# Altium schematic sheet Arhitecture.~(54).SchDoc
size A3; SheetNumber: 1; SheetTotal: 14
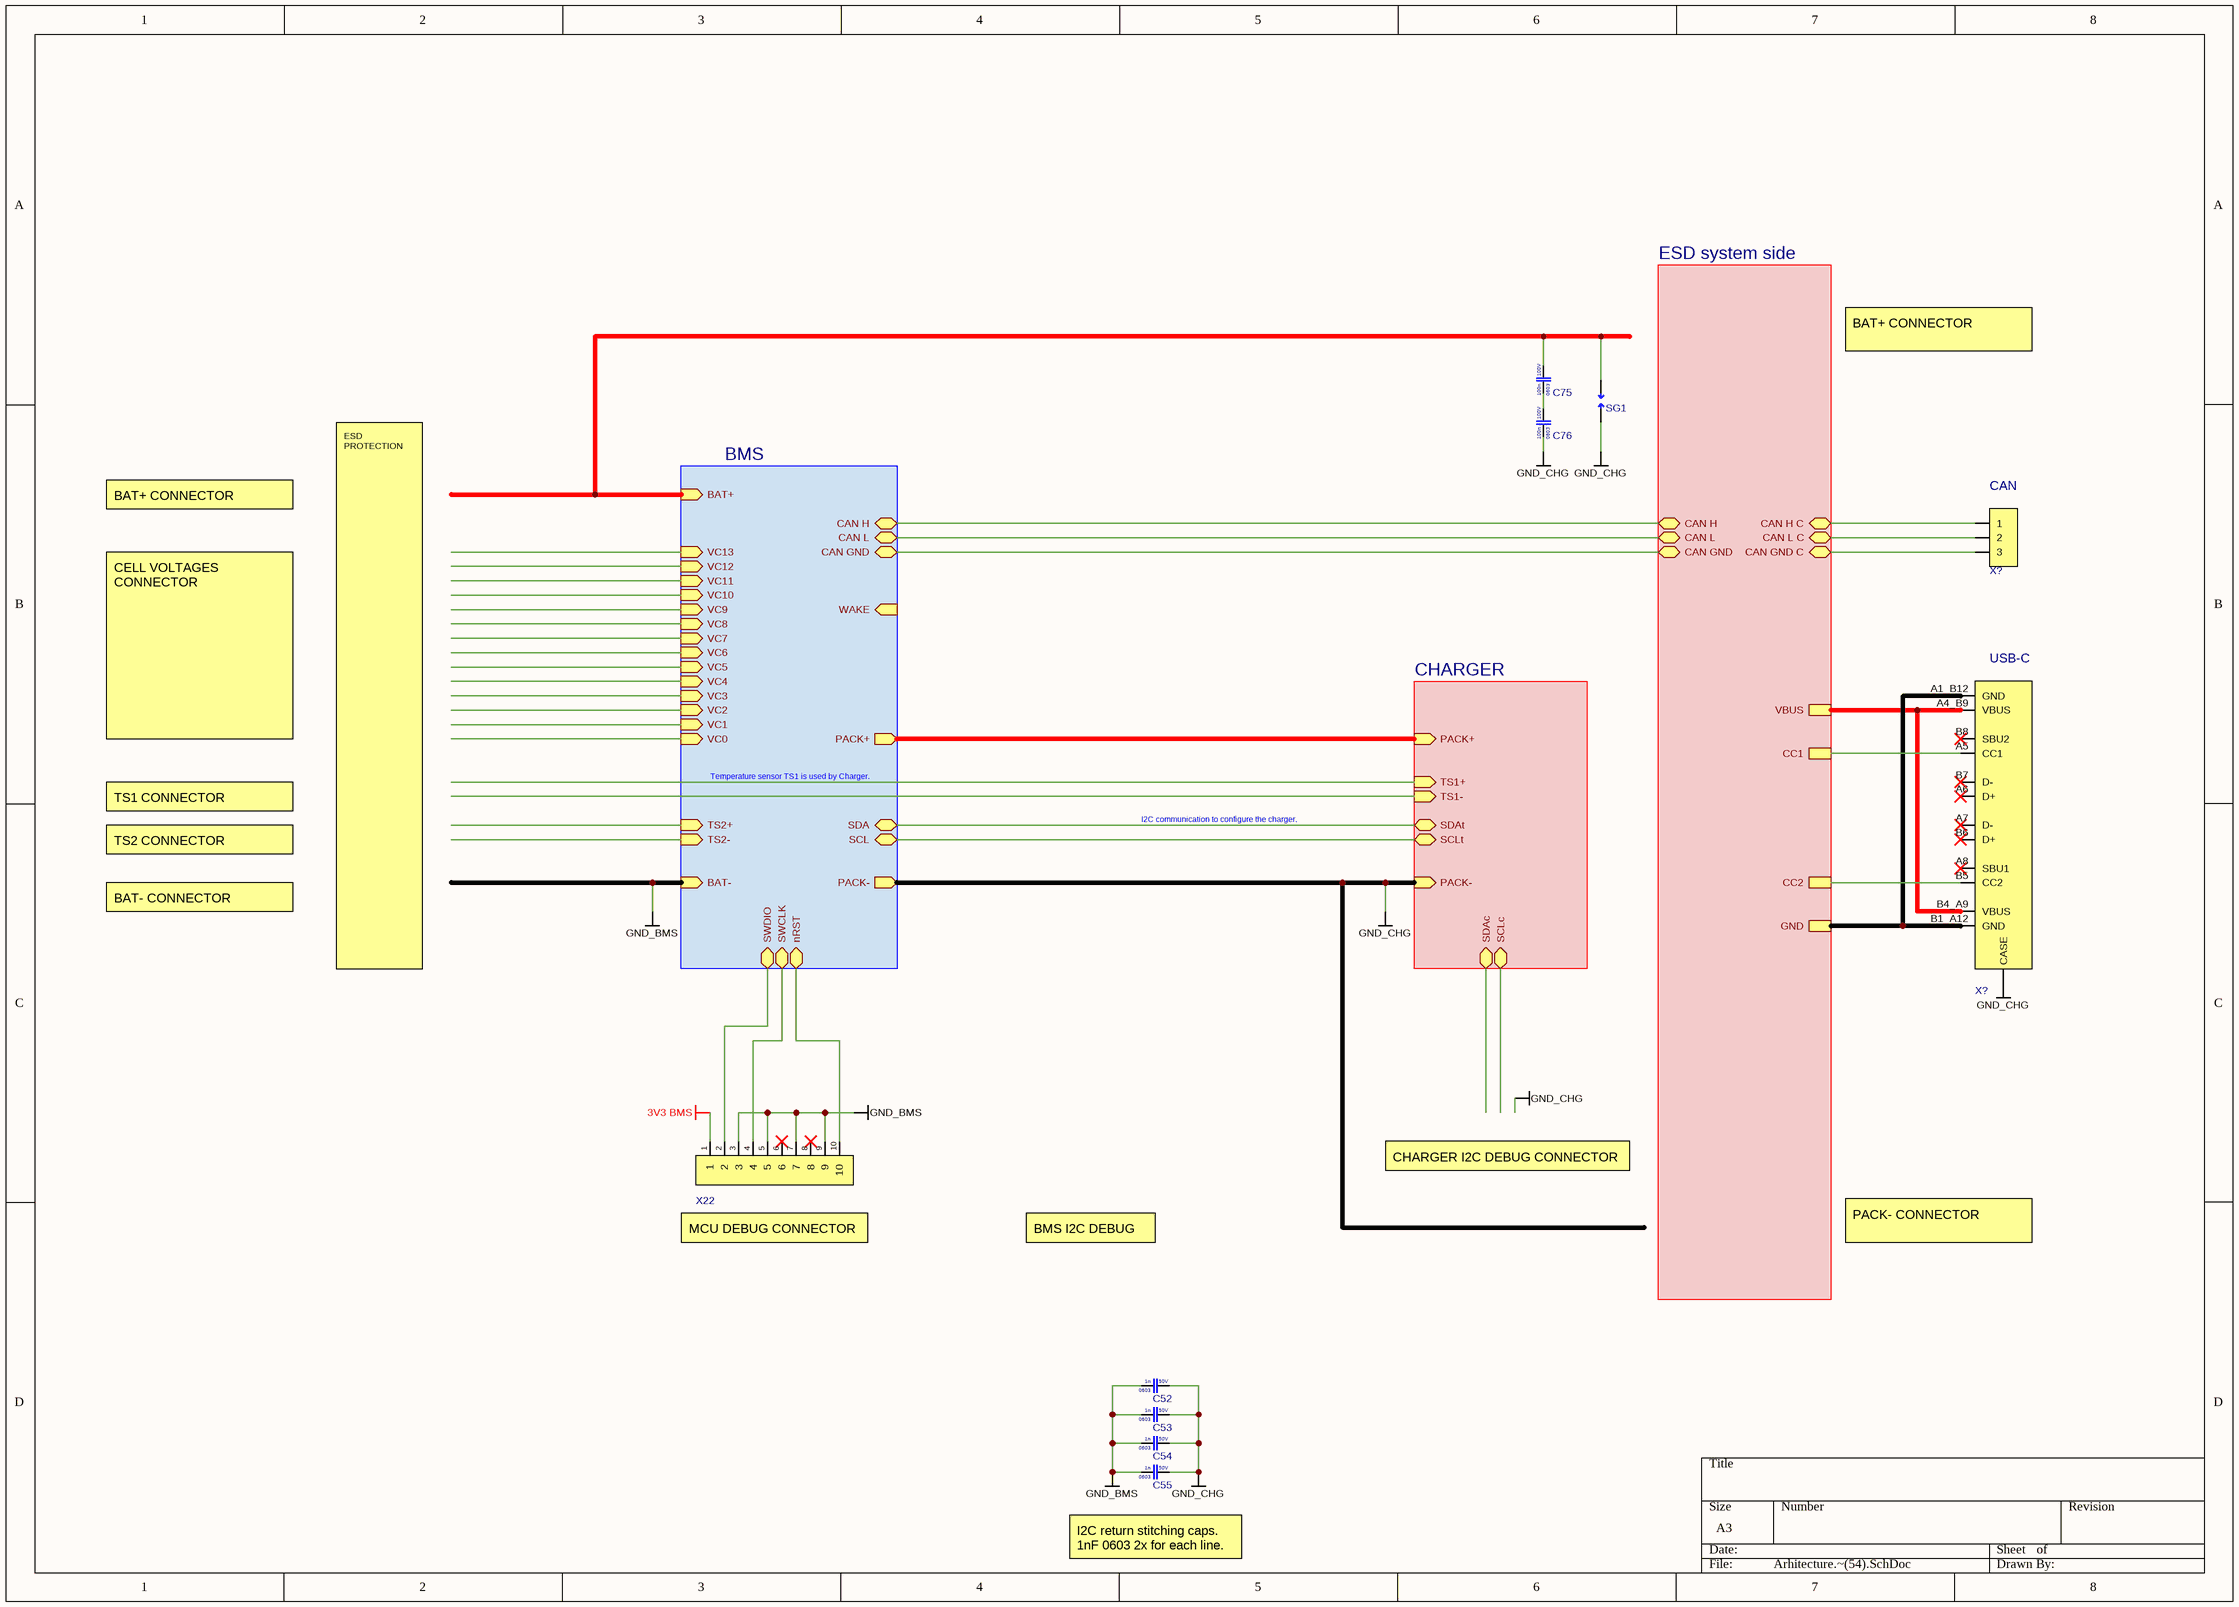
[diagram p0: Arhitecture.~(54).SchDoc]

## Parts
(Parts that share a designator on the sheet are numbered #1, #2 ... from top to bottom, then left to right.)
C52  Voltage Rating: 50V  Case Code (Imperial): 0603  Capacitance: 1n  [CAP 0603]  (hidden comment: CL10B102KB8NNNC)
C53  Voltage Rating: 50V  Case Code (Imperial): 0603  Capacitance: 1n  [CAP 0603]  (hidden comment: CL10B102KB8NNNC)
C54  Voltage Rating: 50V  Case Code (Imperial): 0603  Capacitance: 1n  [CAP 0603]  (hidden comment: CL10B102KB8NNNC)
C55  Voltage Rating: 50V  Case Code (Imperial): 0603  Capacitance: 1n  [CAP 0603]  (hidden comment: CL10B102KB8NNNC)
C75  Voltage Rating: 100V  Case Code (Imperial): 0603  Capacitance: 100n  [CAP 0603]  (hidden comment: CC0603KRX7R0BB104)
C76  Voltage Rating: 100V  Case Code (Imperial): 0603  Capacitance: 100n  [CAP 0603]  (hidden comment: CC0603KRX7R0BB104)
SG1  Spark gap  [Spark Gap 0.270mm]  (value not drawn)  (no BOM)
X22  HX IDC127-2-05-S-4.9  [JTAG Cortex connector]  (value not drawn)
X?#1  S3B-XH-A-1(LF)(SN)  [S3B-XH-A-1(LF)(SN)]  (value not drawn)
X?#2  USB-TYPE-C-018  [TYPE-C 16PIN 2MD]  (value not drawn)

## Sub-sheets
BMS = BMS.SchDoc: BAT+ (in), BAT- (in), VC0 (in), VC1 (in), VC2 (in), VC3 (in), VC4 (in), VC5 (in), VC6 (in), VC7 (in), VC8 (in), VC9 (in), VC10 (in), VC11 (in), VC12 (in), VC13 (in), PACK+ (out), PACK- (out), SCL (bidir), SDA (bidir), CAN H (bidir), CAN L (bidir), TS2+ (in), TS2- (in), WAKE (in), SWDIO (bidir), SWCLK (bidir), nRST (bidir), CAN GND (bidir)
CHARGER = CHARGER.SchDoc: PACK+ (in), PACK- (in), SDAt (bidir), SCLt (bidir), TS1+ (in), TS1- (in), SDAc (bidir), SCLc (bidir)
ESD system side = ESD system side.SchDoc: CAN H (bidir), CAN L (bidir), CAN GND (bidir), CAN H C (bidir), CAN L C (bidir), CAN GND C (bidir), VBUS, GND, CC1, CC2

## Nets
3V3 BMS: X22.1
GND_BMS: C52.1 C53.1 C54.1 C55.1 X22.3 X22.5 X22.7 X22.9 ; sheet BMS/BAT-
GND_CHG: C52.2 C53.2 C54.2 C55.2 C76.1 SG1.1 X?#2.CASE ; sheet BMS/PACK-, sheet CHARGER/PACK-
NetC75_1: C75.1 C76.2
NetC75_2: C75.2 SG1.2 ; sheet BMS/BAT+
NetX22_2: X22.2 ; sheet BMS/SWDIO
NetX22_4: X22.4 ; sheet BMS/SWCLK
NetX22_10: X22.10 ; sheet BMS/nRST
NetX?#1_1: X?#1.1 ; sheet ESD system side/CAN H C
NetX?#1_2: X?#1.2 ; sheet ESD system side/CAN L C
NetX?#1_3: X?#1.3 ; sheet ESD system side/CAN GND C
NetX?#2_A1_B12: X?#2.A1_B12(GND) X?#2.B1_A12(GND) ; sheet ESD system side/GND
NetX?#2_A4_B9: X?#2.A4_B9(VBUS) X?#2.B4_A9(VBUS) ; sheet ESD system side/VBUS
NetX?#2_A5: X?#2.A5(CC1) ; sheet ESD system side/CC1
NetX?#2_B5: X?#2.B5(CC2) ; sheet ESD system side/CC2
(unnamed): sheet BMS/PACK+, sheet CHARGER/PACK+
(unnamed): sheet BMS/SCL, sheet CHARGER/SCLt  [a separate net that carries the same name]
(unnamed): sheet BMS/SDA, sheet CHARGER/SDAt  [a separate net that carries the same name]
(unnamed): sheet BMS/CAN H, sheet ESD system side/CAN H  [a separate net that carries the same name]
(unnamed): sheet BMS/CAN L, sheet ESD system side/CAN L  [a separate net that carries the same name]
(unnamed): sheet BMS/CAN GND, sheet ESD system side/CAN GND  [a separate net that carries the same name]

Not connected (* = marked no-connect by the designer): X22 6* 8*; X?#2 A6(D+)* A7(D-)* A8(SBU1)* B6(D+)* B7(D-)* B8(SBU2)*

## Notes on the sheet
- BAT+ CONNECTOR
- (near X?#1) CAN
- (near X?#2) USB-C
- CELL VOLTAGES CONNECTOR
- TS1 CONNECTOR
- Temperature sensor TS1 is used by Charger.
- I2C communication to configure the charger.
- BAT- CONNECTOR
- TS2 CONNECTOR
- ESD PROTECTION
- CHARGER I2C DEBUG CONNECTOR
- MCU DEBUG CONNECTOR
- BMS I2C DEBUG CONNECTOR
- PACK- CONNECTOR
- (near C55) I2C return stitching caps.
  1nF 0603 2x for each line.

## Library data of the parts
C52-C55 = CL10B102KB8NNNC: Cap 1nF 50V 0603 X7R; Manufacturer: Samsung
C75 C76 = CC0603KRX7R0BB104: Cap 100nF 100V 0603 X7R; Manufacturer: YAGEO
SG1 = Spark gap: Generic Spark gap symbol
X22 = HX IDC127-2-05-S-4.9: JTAG Cortex MCU Debug connector 2x5P 1.27mmP; Manufacturer: hanxia
X?#1 = S3B-XH-A-1(LF)(SN): JST XH 1x3 2.50mmP THT Right-angle
X?#2 = USB-TYPE-C-018: USB-C 16P Right-angle; Manufacturer: DEALON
